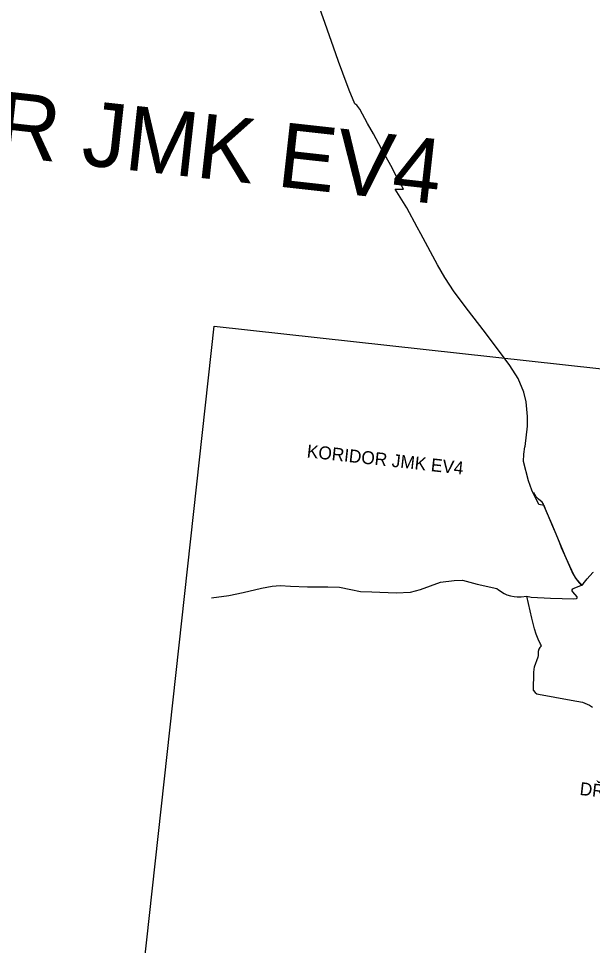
# Model space of a CAD drawing. Extents: x -678204 to -526855, y -1228851 to -1110393.
# Drawn here: x -613531 to -610864, y -1142888 to -1138582 of the extents above; entities that cross this region are included whole.
import ezdxf

# ---------------------------------------------------------------- set-up
doc = ezdxf.new("R2010")
doc.units = 0
for name, color, linetype in [('00_n_cyklo popisy', 7, 'Continuous'), ('00_n_cyklo popisy detaily', 7, 'Continuous'), ('00_n_cyklo prujezdne rekreacni hlavni', 7, 'Continuous'), ('00_n_cyklo prujezdne rekreacni vedlejsi', 7, 'Continuous'), ('00_n_cyklo trasovani rekreacni hlavni', 7, 'Continuous'), ('00_n_cyklo trasovani rekreacni vedlejsi', 7, 'Continuous'), ('_HELP', 7, 'Continuous')]:
    doc.layers.add(name, color=color, linetype=linetype)

msp = doc.modelspace()

# ---------------------------------------------------------------- linework, layer by layer
at = {"layer": '00_n_cyklo prujezdne rekreacni hlavni'}
for points in [[(-612057, -1138746.5), (-612106, -1138605.2), (-612145.7, -1138490.2), (-612170.1, -1138419.7), (-612187.3, -1138368.9)], [(-611678.2, -1139551.6), (-611726.4, -1139462.5), (-611781.4, -1139375.2), (-611741.5, -1139375.5), (-611769.5, -1139325.3), (-611801.1, -1139265.3), (-611844.2, -1139187.4), (-611882.2, -1139117.8), (-611909, -1139070.4), (-611945.4, -1139003.7), (-611958.6, -1138984.1), (-611967.6, -1138978.6), (-611994.3, -1138914.8), (-612023.9, -1138836.2), (-612044.5, -1138782.4), (-612057, -1138746.5)], [(-611177.6, -1140569.7), (-611166.3, -1140476.3), (-611166.6, -1140430.9), (-611172.8, -1140362.9), (-611182.4, -1140317.8), (-611208.8, -1140254), (-611247.8, -1140193.8), (-611291.3, -1140134.5), (-611372.8, -1140029.2), (-611440.1, -1139940.2), (-611507, -1139852), (-611550.2, -1139785.3), (-611583.7, -1139726.3), (-611661.6, -1139582.3), (-611678.2, -1139551.6)], [(-610911.7, -1141216.8), (-610911.6, -1141216.7), (-610941.4, -1141181.3), (-610958.3, -1141152.2), (-610987.2, -1141089.6), (-611017.8, -1141014.2), (-611052.9, -1140929.7), (-611080, -1140869.1), (-611088.8, -1140843.9), (-611113.5, -1140839.1), (-611145.4, -1140772.7), (-611161.2, -1140729.2), (-611185, -1140639.6), (-611183.4, -1140606.5), (-611177.9, -1140572), (-611177.6, -1140569.7)], [(-610915.2, -1141213.8), (-610923.2, -1141205), (-610932.3, -1141193.9), (-610939.8, -1141184.2), (-610946.4, -1141174.5), (-610960.1, -1141147.1), (-610977.4, -1141109.8), (-611008.3, -1141041.8), (-611016.3, -1141019.3), (-611021.8, -1141003.4), (-611032.2, -1140976.9), (-611048.2, -1140942.7), (-611073.2, -1140883.4), (-611088.3, -1140847.1), (-611093.8, -1140834.9), (-611098.5, -1140829), (-611115.5, -1140814.9), (-611126.2, -1140803.6), (-611132, -1140793.2), (-611136.8, -1140784.2)], [(-610915.2, -1141213.8), (-610914.1, -1141213.4), (-610907.7, -1141209), (-610888.2, -1141184.8), (-610862.4, -1141156.2), (-610859.6, -1141153.6)]]:
    msp.add_lwpolyline(points, dxfattribs=at)
at = {"layer": '00_n_cyklo prujezdne rekreacni vedlejsi'}
for points in [[(-612633.9, -1141272.9), (-612553.8, -1141262.6), (-612487.3, -1141249.1), (-612401.4, -1141228.9), (-612351.7, -1141218.8), (-612315.5, -1141215.4), (-612267.5, -1141218.8), (-612188.3, -1141222.1), (-612093.1, -1141222.1), (-612039.2, -1141223.8), (-611986.2, -1141234.8), (-611942.4, -1141243.2), (-611889.3, -1141244.9), (-611776.5, -1141250.8), (-611709.9, -1141246.6), (-611663.6, -1141234.8), (-611571, -1141200.2), (-611506.1, -1141192.7), (-611468.2, -1141191.8), (-611400, -1141209.5), (-611309, -1141230.6), (-611300.5, -1141236.6), (-611273.9, -1141253.9), (-611262.6, -1141258.9), (-611245, -1141264.1), (-611227.9, -1141267.4), (-611213.6, -1141269.3), (-611194.9, -1141268.5), (-611168.5, -1141266.3)], [(-611168.5, -1141266.3), (-611149.2, -1141270.3), (-611059.5, -1141274.5), (-610950.6, -1141277.5), (-610937.7, -1141276.7), (-610935, -1141274.7), (-610935, -1141269.2), (-610955.9, -1141245.6), (-610958.6, -1141241.2), (-610958.3, -1141235.7), (-610955.3, -1141231), (-610949.8, -1141227.7), (-610915.2, -1141213.8)], [(-611100.7, -1141496.8), (-611106.4, -1141488.9), (-611116.9, -1141465.4), (-611126.6, -1141442.6), (-611134.3, -1141416.8), (-611146.2, -1141368.1), (-611168.9, -1141266.3)], [(-611100.8, -1141496.7), (-611108.5, -1141504.7), (-611113.8, -1141512.4), (-611116.2, -1141521.8), (-611116, -1141541), (-611118.2, -1141549), (-611134.7, -1141595.8), (-611136.6, -1141605.4), (-611138.8, -1141619.7), (-611139.3, -1141702.1)], [(-611139.3, -1141702.1), (-611130.9, -1141712.5), (-611122.9, -1141718.7), (-611114.9, -1141721), (-610963.9, -1141748.6), (-610911.3, -1141758.4), (-610889.5, -1141766.7), (-610878.5, -1141771.9), (-610868.4, -1141777.4), (-610864.3, -1141780.6)]]:
    msp.add_lwpolyline(points, dxfattribs=at)
at = {"layer": '00_n_cyklo trasovani rekreacni hlavni'}
for points in [[(-612057, -1138746.5), (-612106, -1138605.2), (-612145.7, -1138490.2), (-612170.1, -1138419.7), (-612187.3, -1138368.9)], [(-611678.2, -1139551.6), (-611726.4, -1139462.5), (-611781.4, -1139375.2), (-611741.5, -1139375.5), (-611769.5, -1139325.3), (-611801.1, -1139265.3), (-611844.2, -1139187.4), (-611882.2, -1139117.8), (-611909, -1139070.4), (-611945.4, -1139003.7), (-611958.6, -1138984.1), (-611967.6, -1138978.6), (-611994.3, -1138914.8), (-612023.9, -1138836.2), (-612044.5, -1138782.4), (-612057, -1138746.5)], [(-611177.6, -1140569.7), (-611166.3, -1140476.3), (-611166.6, -1140430.9), (-611172.8, -1140362.9), (-611182.4, -1140317.8), (-611208.8, -1140254), (-611247.8, -1140193.8), (-611291.3, -1140134.5), (-611372.8, -1140029.2), (-611440.1, -1139940.2), (-611507, -1139852), (-611550.2, -1139785.3), (-611583.7, -1139726.3), (-611661.6, -1139582.3), (-611678.2, -1139551.6)], [(-610911.7, -1141216.8), (-610911.6, -1141216.7), (-610941.4, -1141181.3), (-610958.3, -1141152.2), (-610987.2, -1141089.6), (-611017.8, -1141014.2), (-611052.9, -1140929.7), (-611080, -1140869.1), (-611088.8, -1140843.9), (-611113.5, -1140839.1), (-611145.4, -1140772.7), (-611161.2, -1140729.2), (-611185, -1140639.6), (-611183.4, -1140606.5), (-611177.9, -1140572), (-611177.6, -1140569.7)], [(-610915.2, -1141213.8), (-610923.2, -1141205), (-610932.3, -1141193.9), (-610939.8, -1141184.2), (-610946.4, -1141174.5), (-610960.1, -1141147.1), (-610977.4, -1141109.8), (-611008.3, -1141041.8), (-611016.3, -1141019.3), (-611021.8, -1141003.4), (-611032.2, -1140976.9), (-611048.2, -1140942.7), (-611073.2, -1140883.4), (-611088.3, -1140847.1), (-611093.8, -1140834.9), (-611098.5, -1140829), (-611115.5, -1140814.9), (-611126.2, -1140803.6), (-611132, -1140793.2), (-611136.8, -1140784.2)], [(-610915.2, -1141213.8), (-610914.1, -1141213.4), (-610907.7, -1141209), (-610888.2, -1141184.8), (-610862.4, -1141156.2), (-610859.6, -1141153.6)]]:
    msp.add_lwpolyline(points, dxfattribs=at)
at = {"layer": '00_n_cyklo trasovani rekreacni vedlejsi'}
for points in [[(-612633.9, -1141272.9), (-612553.8, -1141262.6), (-612487.3, -1141249.1), (-612401.4, -1141228.9), (-612351.7, -1141218.8), (-612315.5, -1141215.4), (-612267.5, -1141218.8), (-612188.3, -1141222.1), (-612093.1, -1141222.1), (-612039.2, -1141223.8), (-611986.2, -1141234.8), (-611942.4, -1141243.2), (-611889.3, -1141244.9), (-611776.5, -1141250.8), (-611709.9, -1141246.6), (-611663.6, -1141234.8), (-611571, -1141200.2), (-611506.1, -1141192.7), (-611468.2, -1141191.8), (-611400, -1141209.5), (-611309, -1141230.6), (-611300.5, -1141236.6), (-611273.9, -1141253.9), (-611262.6, -1141258.9), (-611245, -1141264.1), (-611227.9, -1141267.4), (-611213.6, -1141269.3), (-611194.9, -1141268.5), (-611168.5, -1141266.3)], [(-611168.5, -1141266.3), (-611149.2, -1141270.3), (-611059.5, -1141274.5), (-610950.6, -1141277.5), (-610937.7, -1141276.7), (-610935, -1141274.7), (-610935, -1141269.2), (-610955.9, -1141245.6), (-610958.6, -1141241.2), (-610958.3, -1141235.7), (-610955.3, -1141231), (-610949.8, -1141227.7), (-610915.2, -1141213.8)], [(-611100.7, -1141496.8), (-611106.4, -1141488.9), (-611116.9, -1141465.4), (-611126.6, -1141442.6), (-611134.3, -1141416.8), (-611146.2, -1141368.1), (-611168.9, -1141266.3)], [(-611100.8, -1141496.7), (-611108.5, -1141504.7), (-611113.8, -1141512.4), (-611116.2, -1141521.8), (-611116, -1141541), (-611118.2, -1141549), (-611134.7, -1141595.8), (-611136.6, -1141605.4), (-611138.8, -1141619.7), (-611139.3, -1141702.1)], [(-611139.3, -1141702.1), (-611130.9, -1141712.5), (-611122.9, -1141718.7), (-611114.9, -1141721), (-610963.9, -1141748.6), (-610911.3, -1141758.4), (-610889.5, -1141766.7), (-610878.5, -1141771.9), (-610868.4, -1141777.4), (-610864.3, -1141780.6)]]:
    msp.add_lwpolyline(points, dxfattribs=at)
at = {"layer": '_HELP'}
msp.add_lwpolyline([(-612622, -1140011.8), (-607907.5, -1140529.5), (-608276.1, -1143887), (-612990.7, -1143369.3)], close=True, dxfattribs=at)

# ---------------------------------------------------------------- texts
at = {"layer": '00_n_cyklo popisy'}
msp.add_text('KORIDOR JMK EV4', height=300, rotation=353.6836, dxfattribs=at).set_placement((-615215.7, -1139042.8))
at = {"layer": '00_n_cyklo popisy detaily'}
for s, p in [('KORIDOR JMK EV4', (-612193.4, -1140620.7)), ('DŘEVOPLAC', (-610925.8, -1142188.7))]:
    msp.add_text(s, height=60, rotation=353.6836, dxfattribs=at).set_placement(p)

doc.saveas('drawing.dxf')
